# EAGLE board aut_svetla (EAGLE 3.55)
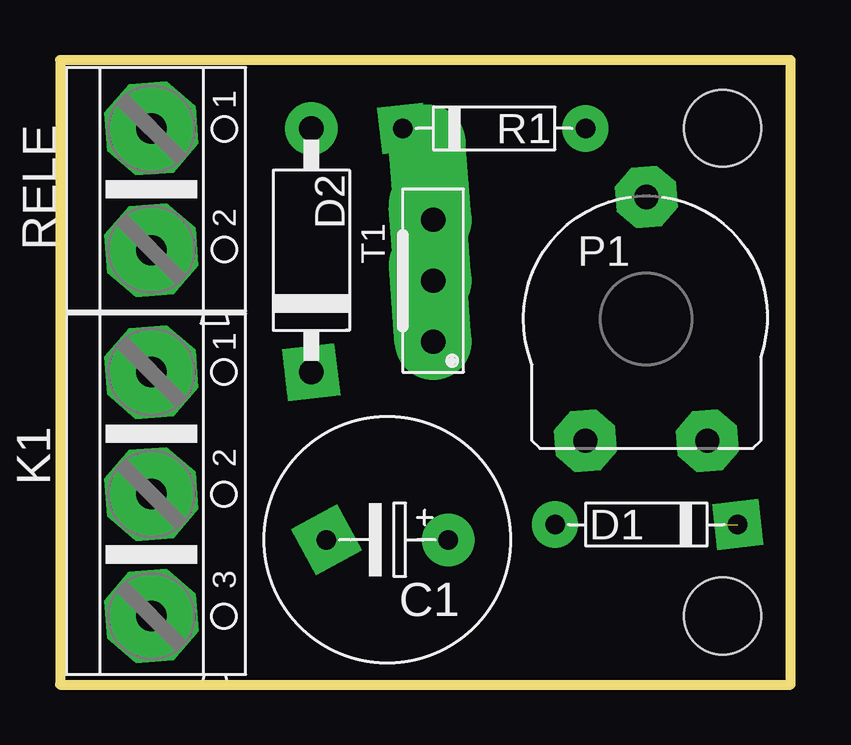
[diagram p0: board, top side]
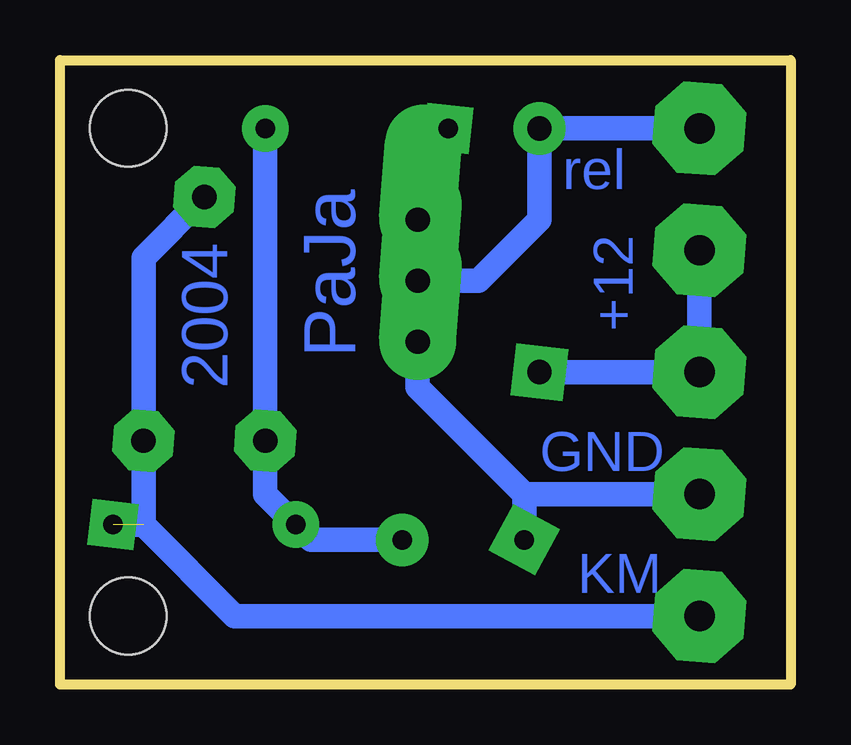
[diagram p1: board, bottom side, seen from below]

Size 30.47 x 26.02 mm. Coordinates in mm from the lower left corner, seen from the top.
Outline: 0,0 30.47,0 30.47,26.02 0,26.02 0,0
Copper layers used: Bottom
Holes 3.2 mm at 27.62,23.18 27.62,2.86

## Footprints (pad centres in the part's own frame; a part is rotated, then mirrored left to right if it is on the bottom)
EL_5 = drill 0.813 pad 2.184 square:  2.54,0 | drill 0.813 pad 2.184 round:  -2.54,0
7,5 = drill 0.813 pad 1.93 square:  3.81,0 | drill 0.813 pad 1.93 round:  -3.81,0
10 = drill 1.016 pad 2.184 square:  5.08,0 | drill 1.016 pad 2.184 round:  -5.08,0
K500/3 = drill 1.27 pad 3.81 octagon:  0,0;  -5.08,0;  5.08,0
10V = drill 1.016 pad 2.54 octagon:  -2.54,-5.08;  2.54,-5.08;  0,5.08
K500/2 = drill 1.27 pad 3.81 octagon:  -2.54,0;  2.54,0
-126S = drill 1.016 pad 3.2 offset:  -2.54,0;  0,0;  2.54,0

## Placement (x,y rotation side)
C1  470M/25V  [EL_5]  13.65,6.03 180 top
D1  1N4148  [7,5]  24.45,6.67 0 top
D2  1N4007  [10]  10.48,18.1 270 top
K1  in  [K500/3]  3.81,7.94 270 top
P1  68k  [10V]  24.45,15.24 0 top
R1  2k7  [7,5]  18.1,23.18 180 top
RELE  12V  [K500/2]  3.81,20.64 270 top
T1  BD681  [-126S]  15.56,16.83 90 top

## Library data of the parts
C1 = #PaJa_C-
D1 D2 K1 P1 R1 RELE T1 = #PaJa_92

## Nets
+12V: D2. K1. RELE.
GND: C1. K1. T1.
KM: D1. K1. P1.
N$1: C1. D1. P1. R1.
N$2: R1. T1.
N$5: D2. RELE. T1.

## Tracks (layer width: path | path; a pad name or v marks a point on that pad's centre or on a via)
+12V
  Bottom 1.016: RELE. 3.81,13.02 10.48,13.02
GND
  Bottom 1.016: 3.81,7.94 11.11,7.94 | 11.11,7.94 11.11,6.03 | 11.11,7.94 15.56,12.38 15.56,14.29
KM  (1 unrouted)
  Bottom 1.016: 26.99,6.67 26.99,10.16 26.99,17.78 P1. | 26.99,6.67 28.26,6.67 | K1. 23.18,2.86 26.99,6.67
N$1
  Bottom 1.016: C1. 20,6.03 D1. 21.91,7.94 21.91,10.16 R1.
N$2
  Bottom 1.016: 14.29,23.18 15.56,21.91 T1.
N$5
  Bottom 1.016: 3.81,23.18 D2. 10.48,19.37 13.02,16.83 15.56,16.83

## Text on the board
Bottom: rel | PaJa | +12 | 2004 | GND | KM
